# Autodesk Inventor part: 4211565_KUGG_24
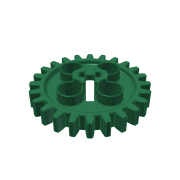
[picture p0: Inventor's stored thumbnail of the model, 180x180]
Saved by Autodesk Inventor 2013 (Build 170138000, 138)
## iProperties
Created: 2013-03
Part Number: 4211565_KUGG_24
Material: Generic
Document SubType Name: Modeling
Designer: perblt
Density: 1 g/cm^3
Translation Standard: STEP AP203
FileName: 4211565_KUGG_24
PreProcessor: PRO/ENGINEER BY PARAMETRIC TECHNOLOGY CORPORATION, 2010370
PostProcessor: Build: 138, Release: 2013 RTM - Date: Thu 03/01/2012
Sent Units: millimeter
Uncertainty: 0.003707617768485
Author: perblt
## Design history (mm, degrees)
node "4211565_KUGG_241"
fillet "Fillet1" dims "d0" = 0.1, "d1" = 0.1
node "4211565_KUGG_24"
node "Base1"
